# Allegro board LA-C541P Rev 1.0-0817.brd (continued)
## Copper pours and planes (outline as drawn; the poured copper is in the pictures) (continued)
N27229608 on BOTTOM (solid shape): 242.54,60.57 243.23,60.57 243.32,60.48 243.32,59.58 243.3,59.55 242.42,59.55 242.16,59.81 242.16,60.25 242.16,60.25 242.16,60.38 242.02,60.52 241.13,60.52 241.06,60.58 241.06,60.67 241.13,60.73 242.38,60.73
N27229638 on BOTTOM (solid shape): 237.92,61.91 237.92,60.55 237.84,60.47 236.93,60.47 236.8,60.6 236.8,61.88 236.89,61.96 237.87,61.96
N27236350 on BOTTOM (solid shape): 233.53,57.12 233.53,56.34 233.65,56.22 235.67,56.22 235.86,56.03 235.86,55.52 236.12,55.27 237.07,55.27 237.92,54.42 237.92,51.87 237.82,51.77 236.05,51.77 234.66,50.38 232.5,50.38 231.99,50.88 231.99,52.28 234.53,52.28 234.53,53.17 231.99,53.17 231.99,57.13 232.15,57.29 233.37,57.29
N27236354 on BOTTOM (solid shape): 237.65,57.95 237.65,56.27 237.45,56.07 236.58,56.07 235.8,56.85 234.89,56.85 234.7,57.05 234.7,57.54 234.78,57.61 236.24,57.61 236.71,58.08 237.52,58.08
N27236394 on BOTTOM (solid shape): 235.53,48.53 235.53,47.9 235.28,47.65 233.44,47.65 233.31,47.77 233.31,48.66 233.44,48.79 235.28,48.79
N27236502 on BOTTOM (solid shape): 244.64,51.5 244.64,49.4 244.58,49.34 243.95,49.34 243.88,49.4 243.88,51.5 243.95,51.56 244.58,51.56
N27236514 on BOTTOM: 241.09,51.64 241.03,51.58 241.03,51.49 241.09,51.43 241.64,51.43 241.77,51.3 241.77,50.97 241.64,50.84 241.09,50.84 241.03,50.78 241.03,50.7 241.09,50.63 243.01,50.63 243.01,50.63 243.19,50.63 243.26,50.69 243.26,51.56 243.17,51.64
N27236522 on BOTTOM (solid shape): 243.24,50.29 243.24,49.45 243.14,49.35 242.44,49.35 242.33,49.45 242.33,49.94 242.04,50.23 241.08,50.23 241.02,50.29 241.02,50.38 241.13,50.49 243.05,50.49
N27236552 on BOTTOM (solid shape): 237.91,51.58 237.91,50.24 237.86,50.19 236.88,50.19 236.75,50.31 236.75,51.58 236.82,51.64 237.85,51.64
N27241431 on TOP (solid shape): 229.45,34.88 229.85,34.48 231.86,34.48 231.95,34.39 231.95,34 231.96,33.99 231.96,31.61 231.1,30.75 230.15,30.75 229.9,30.5 229.9,29.99 229.7,29.8 226.66,29.8 226.02,30.44 226.02,32.85 228.56,32.85 228.56,33.74 226.02,33.74 226.02,35.14 226.59,35.71 228.63,35.71
N27241435 on TOP (solid shape): 231.23,30.12 231.23,28.47 231.17,28.4 227.98,28.4 227.84,28.54 227.84,29 228.01,29.17 229.83,29.17 230.09,29.42 230.09,30.12 230.21,30.25 231.1,30.25
N27241475 on TOP (solid shape): 232.61,38.02 232.61,36.82 232.51,36.71 232.02,36.71 231.65,37.09 231.65,38.09 231.8,38.24 232.39,38.24
N27241475 on TOP (solid shape): 229.54,38.12 229.54,37.49 229.29,37.23 227.44,37.23 227.32,37.36 227.32,38.25 227.44,38.37 229.29,38.37
N27241583 on TOP (solid shape): 238.7,36.63 238.7,34.53 238.64,34.47 238.06,34.47 238.01,34.52 238.01,36.69 238.64,36.69
N27241595 on TOP (solid shape): 236.23,35.53 237.29,35.53 237.37,35.44 237.37,34.54 237.27,34.44 236.45,34.44 236.25,34.64 235.06,34.64 235.02,34.68 235.02,34.82 235.1,34.91 235.13,34.91 235.87,34.91 236.12,35.16 235.87,35.42 235.13,35.42 235.09,35.41 235.02,35.48 235.02,35.61 235.09,35.68 236.08,35.68
N27241603 on TOP (solid shape): 237.34,36.55 237.34,35.74 237.29,35.68 236.29,35.68 236.14,35.83 236.09,35.83 235.08,35.83 235.02,35.9 235.02,36.04 235.09,36.11 235.98,36.11 236.48,36.61 237.29,36.61
N27241633 on TOP (solid shape): 231.96,36.02 231.96,34.69 231.9,34.63 230.81,34.63 230.72,34.72 230.72,36.03 230.79,36.1 231.88,36.1
N27245962 on TOP (solid shape): 230.27,13.74 231.9,13.74 231.94,13.7 231.94,11.01 231.58,10.64 230.73,10.64 230.52,10.43 230.15,10.43 229.9,10.18 229.9,9.67 229.7,9.48 226.66,9.48 226.02,10.12 226.02,12.53 228.56,12.53 228.56,13.42 226.02,13.42 226.02,14.82 226.53,15.32 228.69,15.32
N27245966 on TOP (solid shape): 230.32,9.14 231.17,9.14 231.23,9.09 231.23,7.43 231.06,7.26 230.31,7.26 229.87,6.83 229.21,6.83 228.82,7.22 228.82,8.21 228.82,8.21 228.82,8.78 228.88,8.85 229.83,8.85 230.14,9.15 230.31,9.15
N27246006 on TOP (solid shape): 232.6,17.32 232.6,16.05 232.54,15.99 232.22,15.99 231.7,16.51 231.7,17.28 231.88,17.45 232.47,17.45
N27246006 on TOP (solid shape): 229.51,17.75 229.51,17.11 229.26,16.86 227.42,16.86 227.29,16.99 227.29,17.88 227.42,18 229.26,18
N27246076 on TOP (solid shape): 238.78,16.23 238.78,14.14 238.71,14.07 238.08,14.07 238.02,14.14 238.02,16.23 238.08,16.3 238.71,16.3
N27246118 on TOP (solid shape): 237.41,15.05 237.41,14.13 237.32,14.04 236.65,14.04 236.54,13.94 235.11,13.94 235.04,14.01 235.04,14.09 235.13,14.18 235.16,14.18 235.9,14.18 236.15,14.43 235.9,14.69 235.16,14.69 235.11,14.69 235.06,14.74 235.06,14.87 235.15,14.97 236.56,14.97 236.69,15.1 237.36,15.1
N27246134 on TOP (solid shape): 237.42,16.26 237.42,15.44 237.26,15.29 236.62,15.29 236.46,15.12 235.09,15.12 235.09,15.12 235.04,15.17 235.04,15.26 235.13,15.35 236.02,15.35 236.35,15.69 236.35,16.33 236.45,16.43 237.26,16.43
N27246164 on TOP (solid shape): 231.93,15.29 231.93,13.98 231.88,13.93 231.06,13.93 230.96,14.02 230.96,15.26 231.05,15.35 231.87,15.35
N27251330 on TOP (solid shape): 230.32,24.27 231.9,24.27 231.97,24.21 231.97,21.46 231.1,20.59 230.15,20.59 229.9,20.34 229.9,19.83 229.7,19.64 226.66,19.64 226.02,20.28 226.02,22.69 228.56,22.69 228.56,23.58 226.02,23.58 226.02,24.98 226.53,25.48 229.1,25.48
N27251334 on TOP (solid shape): 231.23,19.96 231.23,18.31 231.17,18.24 227.98,18.24 227.82,18.41 227.82,18.82 228.01,19.01 229.83,19.01 230.09,19.26 230.09,19.96 230.21,20.09 231.1,20.09
N27251374 on TOP (solid shape): 232.61,27.61 232.61,26.58 232.57,26.54 232.24,26.54 231.75,27.03 231.75,27.56 231.93,27.74 232.48,27.74
N27251374 on TOP (solid shape): 229.51,27.96 229.51,27.33 229.26,27.07 227.42,27.07 227.29,27.2 227.29,28.09 227.42,28.21 229.26,28.21
N27251444 on TOP (solid shape): 238.76,26.68 238.76,24.59 238.7,24.52 238.07,24.52 238,24.59 238,26.68 238.07,26.75 238.7,26.75
N27251486 on TOP (solid shape): 237.43,25.45 237.43,24.7 237.2,24.47 235.09,24.47 235.05,24.51 235.05,24.66 235.11,24.72 235.9,24.72 236.15,24.98 235.9,25.23 235.16,25.23 235.12,25.23 235.05,25.3 235.05,25.46 235.08,25.49 237.39,25.49
N27251502 on TOP (solid shape): 237.39,26.64 237.39,25.84 237.21,25.66 235.12,25.66 235.05,25.74 235.05,25.83 235.11,25.89 236.08,25.89 236.3,26.1 236.3,26.35 236.66,26.71 237.32,26.71
N27251532 on TOP (solid shape): 231.95,25.83 231.95,24.53 231.9,24.48 230.96,24.48 230.84,24.59 230.84,25.84 230.89,25.89 231.89,25.89
N28146095 on TOP: 256.01,26.06 256.2,26.06 256.32,25.94 256.32,25.05 256.39,24.98 256.9,24.98 256.99,25.07 256.99,26.41 256.65,26.75 256.07,26.75 256.01,26.69
N28146139 on TOP (solid shape): 262.42,33.84 262.42,33.21 262.37,33.16 261.92,33.16 261.16,32.4 261.16,31.87 261.09,31.8 260.7,31.8 260.44,31.54 260.44,29.59 260.07,29.23 259.12,29.23 259.06,29.29 259.06,29.42 259.12,29.48 260.01,29.48 260.2,29.67 260.2,31.52 260.06,31.65 260.07,31.66 260.07,32.44 260.22,32.6 260.64,32.6 261.35,33.3 261.35,33.81 261.47,33.94 262.32,33.94
N28146405 on TOP (solid shape): 254.18,33.87 256.06,33.87 256.18,33.75 256.18,33.18 256.06,33.06 253.83,33.06 253.04,33.85 253.04,34.26 253.17,34.39 253.66,34.39
N28308683 on TOP (solid shape): 251.8,22.82 252.56,22.82 252.69,22.69 252.69,21.44 252.33,21.08 249.76,21.08 249.52,21.32 249.52,23.2 249.64,23.32 251.29,23.32
N39410732 on TOP (solid shape): 61.7,14.52 61.7,13.36 61.64,13.29 60.62,13.29 60.56,13.23 60.56,12.91 60.49,12.85 58.97,12.85 58.84,12.97 58.84,14.64 59.41,15.21 61.02,15.21
N45812508 on TOP (solid shape): 77.45,15.39 77.45,14.75 77.58,14.63 78.21,14.63 78.4,14.43 78.4,13.61 78.27,13.48 76.75,13.48 76.56,13.67 76.56,15.39 76.69,15.51 77.32,15.51
N53085144 on BOTTOM (solid shape): 65.79,19.55 65.79,18.89 65.56,18.66 64.85,18.66 64.6,18.42 64.6,16.97 64.54,16.91 63.78,16.91 63.72,16.97 63.72,19.64 63.84,19.77 65.57,19.77
N104731395 on TOP (solid shape): 14.2,57.36 14.2,56.85 15.09,55.96 15.92,55.96 16.04,55.84 16.04,55.65 15.98,55.58 14.49,55.58 13.47,54.57 13.47,53.77 13.25,53.55 12.36,53.55 12.23,53.68 12.23,54.88 12.77,55.42 12.77,55.52 12.77,55.52 12.77,56 13.32,56 13.32,56.55 12.77,56.55 12.77,56.8 13.32,56.8 13.32,57.35 12.77,57.35 12.77,57.71 12.93,57.87 13.69,57.87
N104731470 on TOP (solid shape): 17.19,53.93 17.19,53.17 17.06,53.04 15.6,53.04 15.47,53.17 15.47,53.61 15.54,53.68 16.23,53.68 16.36,53.8 16.36,54 16.43,54.06 17.06,54.06

Small or netless copper shapes (teardrops, artwork), in the pictures only: 42 on TOP, 22 on BOTTOM

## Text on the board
Ref Des/Silkscreen Bottom: PWB P/N: | COPYRIGHT 2015 | REV: A00 | ALL RIGHT RESERVED
User.Comments: YJW-1100 | PARTITION_2 | AAPA0 | LA-C541P | Ken_Yang | 2015-08-17 | 2016-08-17 | +3VALW | +5VALW | GND | +5VS
Ref Des/Silkscreen Top: H9 | H14 | H18 | H7 | H12 | H10 | H13 | H29 | H17 | H23 | M2.5X5L | +
BODY_CENTER: +PWR_SRC | +1.0V_PRIM | +3.3V_RUN | GND | +DOCK_PWR_BAR | +VCC_IO | +VCC_GTU | +VCC_CORE | +VCC_GT | +PWR_SRC_MXM | +5V_ALW | +3.3V_ALW | +VCC_SA
User.35: trace Width | Width/space | Single 50ohm | 8.2mil | 7mil | 5.8mil | 6.7mil | 4.3mil | 4mil | 5mil | 5.8 / 4.2 | 6.7 / 5 | 4.3 / 4.2 | 5 / 4.8 | 4 / 4.5 | 4.3 / 4.7 | 4.6 / 6.6 | 5 / 7 | 4 / 6.5 | 3.5 / 10 | 4.5 / 10 | 4 / 10 | SB_1_45mm-10L(4mil & 5mil 50ohm)_WithOutC_150429 | L1-TOP | L2-GND1 | L3-IN1 | L4-VCC | L5-IN2 | L6-IN3 | L7-GND2 | L8-IN4 | L9-GND3 | L10-BOT | LAYER | NAME | STACKUP: 10 LAYER | 35 ohm | 39 ohm | THICKNESS=1.45mm | 43 ohm | 50 ohm | 75 ohm | 85 ohm | 88 ohm | 90 ohm | 100 ohm
User.36: FIGURE | SIZE | 8.0 | 10.0 | 35.0 | 39.0 | 83.0 | 110.0 | 130.0 | 150.0 | 30.0 | 37.0 | 40.0 | 43.0 | 63.0 | 39.0x28.0 | 39.0x33.0 | 94.0x28.0 | 102.0x28.0 | 102.0x83.0 | 112.0x39.0 | 118.0x30.0 | 55.0x43.0 | DRILL CHART: TOP to BOTTOM | ALL UNITS ARE IN MILS | TOLERANCE | +3.0/-3.0 | +2.0/-2.0 | PLATED | NON-PLATED | QTY | 8339 | 30 | 10 | 18 | 1 | 12 | 2 | 6 | 4 | 9 | 8
